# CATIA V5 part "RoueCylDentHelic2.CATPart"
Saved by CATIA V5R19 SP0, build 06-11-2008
Part number: Roue Cyl Denture Hélicoïdale2
Bounding box of the stored display mesh (mm): x -74.499 to 74.5, y -74.5 to 74.502, z -20.617 to 50
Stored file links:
  U:\Rendu_cfao_elguidj\RoueCylDentHelic2.CATPart
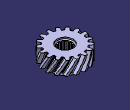
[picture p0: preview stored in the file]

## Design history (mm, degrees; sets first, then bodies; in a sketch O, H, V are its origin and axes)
External parameters (linked from other documents)
  External.Module = 7 mm
  External.Z = 17
  External.DiamPrimitif = 137.4094 mm {= External.ModuleApparent*External.Z}
  External.AnglePression = 20 deg
  External.x = 0
  External.DeportDenture = 0 mm {= External.x *External.ModuleApparent}
  External.DiamBase = 129.1226 mm {= External.DiamPrimitif *cos(External.AnglePression )}
  External.DiamPied = 119.9094 mm {= External.DiamPrimitif -2.5*External.Module +2*External.DeportDenture}
  External.DiamTete = 149 mm
  External.PhiPrimitif = 0.854 deg {= atan((sin(External.ThetaPrimitif*1rad)-External.ThetaPrimitif*cos(External.ThetaPrimitif*1rad))/(cos(External.ThetaPrimitif*1rad)+External.ThetaPrimitif*sin(External.ThetaPrimitif*1rad)))}
  External.PhiTete = 3.058 deg {= atan((sin(External.ThetaTete*1rad)-External.ThetaTete*cos(External.ThetaTete*1rad))/(cos(External.ThetaTete*1rad)+External.ThetaTete*sin(External.ThetaTete*1rad)))}
  External.PhiSymetrie = 5.2941 deg {= 180*1 deg/(2*External.Z )}
  External.CongePied = 2.66 mm {= 0.38*External.Module}
  External.AlphaCopie = 21.1765 deg {= 360*1 deg/External.Z}
  External.AlphaSymetrieCopie = 10.5882 deg {= External.AlphaCopie /2}
  External.LargeurDenture = 50 mm {= 50mm}
  External.ThetaPrimitif = 0.36397 {= sqrt(abs((External.DiamPrimitif*External.DiamPrimitif)/(External.DiamBase *External.DiamBase )-1))}
  External.ThetaTete = 0.575832 {= sqrt(abs((External.DiamTete*External.DiamTete)/(External.DiamBase *External.DiamBase )-1) )}
  External.Di = 133.266 mm {= (External.DiamBase +External.DiamPrimitif )/2}
  External.Thetai = 0.255358 {= sqrt(abs((External.Di*External.Di)/(External.DiamBase*External.DiamBase)-1))}
  External.Phii = 0.3061 deg {= atan((sin(External.Thetai*1rad)-External.Thetai*cos(External.Thetai*1rad))/(cos(External.Thetai*1rad)+External.Thetai*sin(External.Thetai*1rad)))}
  External.Dj = 143.2047 mm {= (External.DiamTete+External.DiamPrimitif)/2}
  External.Thetaj = 0.479598 {= sqrt(abs((External.Dj*External.Dj)/(External.DiamBase*External.DiamBase)-1))}
  External.Phij = 1.8567 deg {= atan((sin(External.Thetaj*1rad)-External.Thetaj*cos(External.Thetaj*1rad))/(cos(External.Thetaj*1rad)+External.Thetaj*sin(External.Thetaj*1rad)))}
  External.Dk = 131.1943 mm {= (External.Di+External.DiamBase)/2}
  External.Thetak = 0.179851 {= sqrt(abs((External.Dk*External.Dk)/(External.DiamBase*External.DiamBase)-1))}
  External.Phik = 0.109 deg {= atan((sin(External.Thetak*1rad)-External.Thetak*cos(External.Thetak*1rad))/(cos(External.Thetak*1rad)+External.Thetak*sin(External.Thetak*1rad)))}
  External.Dl = 135.3377 mm {= (External.DiamPrimitif+External.Di)/2}
  External.Thetal = 0.31398 {= sqrt(abs((External.Dl*External.Dl)/(External.DiamBase*External.DiamBase)-1))}
  External.Phil = 0.5585 deg {= atan((sin(External.Thetal*1rad)-External.Thetal*cos(External.Thetal*1rad))/(cos(External.Thetal*1rad)+External.Thetal*sin(External.Thetal*1rad)))}
  External.Dm = 140.307 mm {= (External.Dj+External.DiamPrimitif)/2}
  External.Thetam = 0.425136 {= sqrt(abs((External.Dm*External.Dm)/(External.DiamBase*External.DiamBase)-1))}
  External.Phim = 1.3264 deg {= atan((sin(External.Thetam*1rad)-External.Thetam*cos(External.Thetam*1rad))/(cos(External.Thetam*1rad)+External.Thetam*sin(External.Thetam*1rad)))}
  External.Dn = 146.1023 mm {= (External.DiamTete+External.Dj)/2}
  External.Thetan = 0.529429 {= sqrt(abs((External.Dn*External.Dn)/(External.DiamBase*External.DiamBase)-1))}
  External.Phin = 2.436 deg {= atan((sin(External.Thetan*1rad)-External.Thetan*cos(External.Thetan*1rad))/(cos(External.Thetan*1rad)+External.Thetan*sin(External.Thetan*1rad)))}
  External.AngleHelice = 30 deg
  External.ModuleApparent = 8.0829 mm {= External.Module /cos(External.AngleHelice )}
  External.SensDenture = 1
  External.LargeurDent = 45 mm {= round(PI*External.Module /sin(External.AngleHelice )/1mm)*1mm+1mm}
Body1 (main body)
  Sketch1 "EsquisseDent" on xy-plane, origin (0, 0, 0), H (1, 0, 0), V (0, 1, 0)
    construction circle A1 centre (0, 0) radius 68.7047
    construction circle A2 centre (0, 0) radius 64.5613
    construction circle A3 centre (0, 0) radius 59.9547
    construction circle A4 centre (0, 0) radius 74.5
    point P1 (64.5613, 0)
    construction line L1 (64.5613, 0) -> (0, 0)
    point P2 (68.6971, 1.024)
    construction line L2 (68.6971, 1.024) -> (0, 0)
    point P3 (74.3939, 3.9744)
    construction line L3 (74.3939, 3.9744) -> (0, 0)
    construction line L4 (64.5613, 0) -> (64.5613, 3.9367)
    point P4 (64.5613, 0)
    point P6 (60.4255, 1.024)
    construction line L5 (74.3939, 3.9744) -> (68.6971, 1.024)
    point P7 (71.5455, 2.4992)
    point P8 (57.5771, 2.4992)
    spline S1 through (57.5771, 2.4992) (60.4255, 1.024) (64.5613, 0) (65.597, 0.1248) (66.632, 0.356) (67.6656, 0.6596) (68.6971, 1.024) (70.1347, 1.6239) (71.5648, 2.3199) (72.9852, 3.1049) (74.3939, 3.9744)
    construction line L6 (0, 0) -> (5.2441, 0.5649)
    spline S2 through (56.7885, 9.82) (59.2574, 11.868) (63.0802, 13.7493) (64.1188, 13.8479) (65.1793, 13.8424) (66.2538, 13.7659) (67.3392, 13.6296) (68.8717, 13.3496) (70.4171, 12.9741) (71.9721, 12.5096) (73.5337, 11.9601)
    arc A5 centre (62.5641, -2.5174) radius 2.66 from (63.0483, 0.0982) to (59.9062, -2.4104) ccw
    point P11 (59.9062, -2.4104)
    arc A6 centre (0, 0) radius 74.5 from (74.3939, 3.9744) to (73.5337, 11.9601) ccw
    point P13 (73.5337, 11.9601)
    arc A7 centre (60.5927, 15.7836) radius 2.66 from (58.0186, 15.113) to (61.6229, 13.3311) ccw
    point P15 (58.0186, 15.113)
    construction line L7 (0, 0) -> (4.1018, 1.2334)
    construction line L8 (0, 0) -> (5.1105, -0.3968)
    point P19 (57.415, 17.265)
    arc A8 centre (0, 0) radius 59.9547 from (58.0186, 15.113) to (57.415, 17.265) ccw
    point P20 (59.7747, -4.6416)
    arc A9 centre (0, 0) radius 59.9547 from (59.7747, -4.6416) to (59.9062, -2.4104) ccw
    line L9 (57.415, 17.265) -> (0, 0)
    line L10 (59.7747, -4.6416) -> (0, 0)
    construction circle A10 centre (0, 0) radius 66.633
    construction line L11 (0, 0) -> (2.5698, 0.0137)
    point P22 (66.632, 0.356)
    construction circle A11 centre (0, 0) radius 71.6023
    construction line L12 (0, 0) -> (4.017, 0.1302)
    point P24 (71.5648, 2.3199)
    point P25 (71.5648, 2.3199)
    point P26 (70.4171, 12.9741)
    point P27 (65.1793, 13.8424)
    construction circle A12 centre (0, 0) radius 65.5971
    construction line L13 (0, 0) -> (48.2618, 0.0918)
    point P29 (64.1188, 13.8479)
    construction line L14 (0, 0) -> (63.6105, 6.852)
    point P31 (65.597, 0.1248)
    construction circle A13 centre (0, 0) radius 67.6688
    construction line L15 (0, 0) -> (57.3607, 0.5591)
    point P33 (67.6656, 0.6596)
    point P34 (66.2538, 13.7659)
    construction circle A14 centre (0, 0) radius 70.1535
    construction line L16 (0, 0) -> (65.6931, 1.5211)
    point P36 (70.1347, 1.6239)
    point P37 (68.8717, 13.3496)
    construction circle A15 centre (0, 0) radius 73.0512
    axis line L17 (0, 0) -> (59.2973, 2.5226)
    point P39 (71.9721, 12.5096)
    point P40 (72.9852, 3.1049)
    point P42 (57.5771, 2.4992)
    point P43 (60.4255, 1.024)
    point P44 (64.5613, 0)
    point P45 (68.6971, 1.024)
    point P46 (74.3939, 3.9744)
    point P47 (73.5337, 11.9601)
    point P48 (56.7885, 9.82)
    point P49 (67.3392, 13.6296)
    point P50 (63.0802, 13.7493)
    point P51 (59.2574, 11.868)
    point P52 (66.632, 0.356)
    point P53 (71.5648, 2.3199)
    point P54 (65.1793, 13.8424)
    point P55 (70.4171, 12.9741)
    point P56 (65.597, 0.1248)
    point P57 (64.1188, 13.8479)
    point P58 (67.6656, 0.6596)
    point P59 (66.2538, 13.7659)
    point P60 (70.1347, 1.6239)
    point P61 (68.8717, 13.3496)
    point P62 (72.9852, 3.1049)
    point P63 (71.9721, 12.5096)
    radius A1 = 68.7047 {= External.DiamPrimitif /2}
    radius A2 = 64.5613 {= External.DiamBase /2}
    radius A3 = 59.9547 {= External.DiamPied /2}
    radius A4 = 74.5 {= External.DiamTete /2}
    angle L2 L1 = 0.854 {= External.PhiPrimitif}
    angle L3 L1 = 3.058 {= External.PhiTete}
    angle L4 L1 = 90
    radius A5 = 2.66 {= External.CongePied}
    radius A7 = 2.66 {= External.CongePied}
    angle L7 L6 = 10.5882 {= External.AlphaSymetrieCopie}
    angle L2 L6 = 5.2941 {= External.PhiSymetrie}
    radius A10 = 66.633 {= External.Di /2}
    angle L11 L1 = 0.3061 {= External.Phii}
    radius A11 = 71.6023 {= External.Dj /2}
    angle L12 L1 = 1.8567 {= External.Phij}
    radius A12 = 65.5971 {= External.Dk/2}
    angle L13 L1 = 0.109 {= External.Phik}
    angle L14 L2 = 5.2941 {= External.PhiSymetrie}
    radius A13 = 67.6688 {= External.Dl /2}
    angle L15 L1 = 0.5585 {= External.Phil}
    radius A14 = 70.1535 {= External.Dm /2}
    angle L16 L1 = 1.3264 {= External.Phim}
    radius A15 = 73.0512 {= External.Dn/2}
    angle L17 L1 = 2.436 {= External.Phin}
    coincidence: P1 A2, P1 H, P2 A1, P3 A4, P4 A2, P7 L5, P42 P8, P43 P6, P44 P1, P45 L5, P45 L2, P46 L5, P46 L3, P11 A3, P47 P13, P15 A3, P19 L7, P19 A3, P20 L8, P20 A3, P3 P46, P22 L11, P22 A10, P52 P22, P24 L12, P24 A11, P53 P24, P25 P53, P54 P27, P55 P26, P31 L13, P31 A12, P56 P31, P57 P29, P33 L15, P33 A13, P58 P33, P59 P34, P36 L16, P36 A14, P60 P36, P61 P37, P40 L17, P40 A15, P62 P40, P63 P39, O L9, O L10
    horizontal: L1 H
    tangency: L4 A2, A5 A3, A5 S1, A7 A3, A7 S2, A8 A5, A9 A5
    symmetry: P6 P2 L4, P8 P7 L4, P46 P47 L6, P42 P48 L6, P45 P49 L6, P44 P50 L6, P43 P51 L6, L8 L7 L6, P26 P25 L6, P27 P22 L6, P29 P31 L14, P34 P33 L14, P37 P36 L14, P39 P40 L14
    midpoint: P7 L5
    parallelism: L9 L7, L10 L8
    concentricity: A10 A2, A11 A1
  Translate1: ToTransfor Sketch1, Direction (0, 0, 1), Length 50 {= External.LargeurDenture}
  Rotate1: ToTransfor Translate1, Axis Z axis, Angle 22.7906 {= External.SensDenture *atan(2*External.LargeurDenture/External.DiamPrimitif*tan(External.AngleHelice))}
  Translate2: ToTransfor Sketch1, Direction (0, 0, 1), Length 25 {= External.LargeurDenture/2}
  Rotate2: ToTransfor Translate2, Axis Z axis, Angle 11.8644 {= External.SensDenture *atan(External.LargeurDenture/(External.DiamPrimitif)*tan(External.AngleHelice))}
  Translate3: ToTransfor Sketch1, Direction (0, 0, 1), Length 37.5 {= 3/4*External.LargeurDenture}
  Rotate3: ToTransfor Translate3, Axis Z axis, Angle 17.491 {= External.SensDenture*atan(3*External.LargeurDenture/(2*External.DiamPrimitif)*tan(External.AngleHelice))}
  Translate4: ToTransfor Sketch1, Direction (0, 0, 1), Length 12.5 {= External.LargeurDenture/4}
  Rotate4: ToTransfor Translate4, Axis Z axis, Angle 5.9965 {= External.SensDenture*atan(External.LargeurDenture/(2*External.DiamPrimitif)*tan(External.AngleHelice))}
  Loft1: solid, Sections (Sketch1; Rotate4; Rotate2; Rotate3; Rotate1)
  CircPattern1: of the body so far, instances 17 {= External.Z}, angular step 21.1765 {= External.AlphaCopie}, axis from Z axis
  Plane1: type Offset, RefPlane xy-plane, Offset 50 {= External.LargeurDenture}, reversed
  Sketch2 on Plane1, origin (0, 0, -50), H (1, 0, 0), V (0, 1, 0)
    circle A1 centre (0, 0) radius 29
    radius A1 = 29 {= int(External.DiamPied/(4mm))*1mm}
  Pocket1: profile Sketch2, direction (0, 0, 1), length 150 {= 3*External.LargeurDenture}
  DatumCurve1 to DatumCurve3
  Sketch3 on yz-plane, origin (0, 0, 0), H (0, 1, 0), V (0, 0, 1)
    point P1 (42.5, 0)
    line L1 (42.5, 0) -> (42.5, -20.617)
    line L2 (42.5, -20.617) -> (29, -20.617)
    point P3 (29, -20.617)
    line L3 (29, -20.617) -> (25, -13.6888)
    line L4 (25, -13.6888) -> (25, 42.6906)
    line L5 (25, 42.6906) -> (29, 45)
    point P6 (29, 45)
    line L6 (42.5, 0) -> (29, 0)
    point P7 (29, 0)
    line L7 (29, 0) -> (29, 45)
    reference projected line E1 (0, -270.203) -> (0, 469.4047) from edge of DatumCurve1
    reference projected line E2 (0, -270.203) -> (0, 469.4047) from edge of DatumCurve2
    point P8 (29, 0)
    reference intersected line E3 (-59.9784, 50) -> (74.5, 50) from face of CircPattern1
    distance L1 E1 = 42.5
    angle L4 L5 = 60
    angle L3 L4 = 30
    length L1 = 20.617
    distance L4 E2 = 25
    distance P6 E3 = 5
    coincidence: P1 H, P7 P8, P3 L7
    vertical: L1 V, L4 V, L7 V
    horizontal: L2 H, L6 H
    fix: P8
  Shaft1: profile Sketch3, axis edge of DatumCurve3, angle 360
  Plane2: stored without definition
  Sketch4 on xy-plane, origin (0, 0, 0), H (1, 0, 0), V (0, 1, 0)
    arc A1 centre (0, 0) radius 20.1556 from (-2.5, 20) to (-5.2167, 19.4689) ccw
    construction line L1 (0, 0) -> (0, 22.1914)
    point P2 (2.5, 24)
    line L2 (2.5, 24) -> (-2.5, 24)
    line L3 (-2.5, 24) -> (-2.5, 20)
    line L4 (2.5, 20) -> (2.5, 24)
    point P3 (-2.5, 24)
    point P4 (2.5, 20)
    point P5 (-2.5, 20)
    construction line L5 (4.2245, -15.766) -> (-5.8305, 21.7596)
    construction line L6 (-5.8201, -21.7207) -> (5.9156, 22.0773)
    construction line L7 (17.7406, -17.7406) -> (-11.7329, 11.7329)
    construction line L8 (16.2956, -4.3664) -> (-15.3401, 4.1104)
    point P14 (-5.2167, 19.4689)
    arc A2 centre (0, 0) radius 20.1556 from (5.2167, 19.4689) to (2.5, 20) ccw
    point P15 (5.2167, 19.4689)
    point P16 (-5.2167, 19.4689)
    point P17 (-7.8349, 18.5705)
    arc A3 centre (0, 0) radius 20.1556 from (-7.8349, 18.5705) to (-5.2167, 19.4689) cw
    point P19 (-9.8349, 22.0346)
    line L9 (-9.8349, 22.0346) -> (-7.8349, 18.5705)
    point P20 (-14.1651, 19.5346)
    line L10 (-14.1651, 19.5346) -> (-9.8349, 22.0346)
    point P21 (-12.1651, 16.0705)
    line L11 (-12.1651, 16.0705) -> (-14.1651, 19.5346)
    point P22 (-14.2522, 14.2522)
    arc A4 centre (0, 0) radius 20.1556 from (-14.2522, 14.2522) to (-12.1651, 16.0705) cw
    point P23 (-20, -2.5)
    point P24 (-19.4689, -5.2167)
    arc A5 centre (0, 0) radius 20.1556 from (-19.4689, -5.2167) to (-20, -2.5) cw
    point P26 (-24, -2.5)
    line L12 (-20, -2.5) -> (-24, -2.5)
    point P27 (-24, 2.5)
    line L13 (-24, -2.5) -> (-24, 2.5)
    point P28 (-20, 2.5)
    line L14 (-24, 2.5) -> (-20, 2.5)
    point P29 (-19.4689, 5.2167)
    arc A6 centre (0, 0) radius 20.1556 from (-20, 2.5) to (-19.4689, 5.2167) cw
    point P30 (-19.4689, 5.2167)
    point P31 (-18.5705, 7.8349)
    arc A7 centre (0, 0) radius 20.1556 from (-18.5705, 7.8349) to (-19.4689, 5.2167) ccw
    point P33 (-22.0346, 9.8349)
    line L15 (-22.0346, 9.8349) -> (-18.5705, 7.8349)
    point P34 (-19.5346, 14.1651)
    line L16 (-19.5346, 14.1651) -> (-22.0346, 9.8349)
    point P35 (-16.0705, 12.1651)
    line L17 (-16.0705, 12.1651) -> (-19.5346, 14.1651)
    point P36 (-14.2522, 14.2522)
    arc A8 centre (0, 0) radius 20.1556 from (-14.2522, 14.2522) to (-16.0705, 12.1651) ccw
    axis line L18 (-19.4689, -5.2167) -> (23.4606, 6.2862)
    point P38 (-7.8349, -18.5705)
    point P39 (-5.2167, -19.4689)
    arc A9 centre (0, 0) radius 20.1556 from (-5.2167, -19.4689) to (-7.8349, -18.5705) cw
    point P41 (-9.8349, -22.0346)
    line L19 (-7.8349, -18.5705) -> (-9.8349, -22.0346)
    point P42 (-14.1651, -19.5346)
    line L20 (-9.8349, -22.0346) -> (-14.1651, -19.5346)
    point P43 (-12.1651, -16.0705)
    line L21 (-14.1651, -19.5346) -> (-12.1651, -16.0705)
    point P44 (-14.2522, -14.2522)
    arc A10 centre (0, 0) radius 20.1556 from (-12.1651, -16.0705) to (-14.2522, -14.2522) cw
    point P45 (-14.2522, -14.2522)
    point P46 (-16.0705, -12.1651)
    arc A11 centre (0, 0) radius 20.1556 from (-16.0705, -12.1651) to (-14.2522, -14.2522) ccw
    point P48 (-19.5346, -14.1651)
    line L22 (-19.5346, -14.1651) -> (-16.0705, -12.1651)
    point P49 (-22.0346, -9.8349)
    line L23 (-22.0346, -9.8349) -> (-19.5346, -14.1651)
    point P50 (-18.5705, -7.8349)
    line L24 (-18.5705, -7.8349) -> (-22.0346, -9.8349)
    point P51 (-19.4689, -5.2167)
    arc A12 centre (0, 0) radius 20.1556 from (-19.4689, -5.2167) to (-18.5705, -7.8349) ccw
    point P52 (7.8349, 18.5705)
    point P53 (5.2167, 19.4689)
    arc A13 centre (0, 0) radius 20.1556 from (5.2167, 19.4689) to (7.8349, 18.5705) cw
    point P55 (9.8349, 22.0346)
    line L25 (7.8349, 18.5705) -> (9.8349, 22.0346)
    point P56 (14.1651, 19.5346)
    line L26 (9.8349, 22.0346) -> (14.1651, 19.5346)
    point P57 (12.1651, 16.0705)
    line L27 (14.1651, 19.5346) -> (12.1651, 16.0705)
    point P58 (14.2522, 14.2522)
    arc A14 centre (0, 0) radius 20.1556 from (12.1651, 16.0705) to (14.2522, 14.2522) cw
    point P59 (14.2522, 14.2522)
    point P60 (16.0705, 12.1651)
    arc A15 centre (0, 0) radius 20.1556 from (16.0705, 12.1651) to (14.2522, 14.2522) ccw
    point P62 (19.5346, 14.1651)
    line L28 (19.5346, 14.1651) -> (16.0705, 12.1651)
    point P63 (22.0346, 9.8349)
    line L29 (22.0346, 9.8349) -> (19.5346, 14.1651)
    point P64 (18.5705, 7.8349)
    line L30 (18.5705, 7.8349) -> (22.0346, 9.8349)
    point P65 (19.4689, 5.2167)
    arc A16 centre (0, 0) radius 20.1556 from (19.4689, 5.2167) to (18.5705, 7.8349) ccw
    point P66 (20, 2.5)
    point P67 (19.4689, 5.2167)
    arc A17 centre (0, 0) radius 20.1556 from (19.4689, 5.2167) to (20, 2.5) cw
    point P69 (24, 2.5)
    line L31 (20, 2.5) -> (24, 2.5)
    point P70 (24, -2.5)
    line L32 (24, 2.5) -> (24, -2.5)
    point P71 (20, -2.5)
    line L33 (24, -2.5) -> (20, -2.5)
    point P72 (19.4689, -5.2167)
    arc A18 centre (0, 0) radius 20.1556 from (20, -2.5) to (19.4689, -5.2167) cw
    point P73 (19.4689, -5.2167)
    point P74 (18.5705, -7.8349)
    arc A19 centre (0, 0) radius 20.1556 from (18.5705, -7.8349) to (19.4689, -5.2167) ccw
    point P76 (22.0346, -9.8349)
    line L34 (22.0346, -9.8349) -> (18.5705, -7.8349)
    point P77 (19.5346, -14.1651)
    line L35 (19.5346, -14.1651) -> (22.0346, -9.8349)
    point P78 (16.0705, -12.1651)
    line L36 (16.0705, -12.1651) -> (19.5346, -14.1651)
    point P79 (14.2522, -14.2522)
    arc A20 centre (0, 0) radius 20.1556 from (14.2522, -14.2522) to (16.0705, -12.1651) ccw
    point P80 (12.1651, -16.0705)
    point P81 (14.2522, -14.2522)
    arc A21 centre (0, 0) radius 20.1556 from (14.2522, -14.2522) to (12.1651, -16.0705) cw
    point P83 (14.1651, -19.5346)
    line L37 (12.1651, -16.0705) -> (14.1651, -19.5346)
    point P84 (7.8349, -18.5705)
    point P85 (9.8349, -22.0346)
    line L38 (9.8349, -22.0346) -> (7.8349, -18.5705)
    point P86 (5.2167, -19.4689)
    arc A22 centre (0, 0) radius 20.1556 from (7.8349, -18.5705) to (5.2167, -19.4689) cw
    point P87 (5.2167, -19.4689)
    point P88 (2.5, -20)
    arc A23 centre (0, 0) radius 20.1556 from (2.5, -20) to (5.2167, -19.4689) ccw
    point P90 (2.5, -24)
    line L39 (2.5, -24) -> (2.5, -20)
    point P91 (-2.5, -24)
    line L40 (-2.5, -24) -> (2.5, -24)
    point P92 (-2.5, -20)
    line L41 (-2.5, -20) -> (-2.5, -24)
    point P93 (-5.2167, -19.4689)
    arc A24 centre (0, 0) radius 20.1556 from (-5.2167, -19.4689) to (-2.5, -20) ccw
    line L42 (14.1651, -19.5346) -> (9.8349, -22.0346)
    circle A25 centre (0, 0) radius 25
    length L3 = 4
    length L4 = 4
    distance L4 L1 = 2.5
    distance H L2 = 24
    angle L8 L7 = 30
    radius A25 = 25
    vertical: L1 V, L3 V, L4 V
    horizontal: L2 H
    coincidence: L5 O, L6 O, L7 O, L8 O, L5 P14, L6 P15, A1 A2, L18 O, P14 P16, P15 P53, P22 P36, P24 P51, P29 P30, P39 P93, P44 P45, P58 P59, P65 P67, P72 P73, P79 P81, P86 P87
    symmetry: P14 P16 L5, P5 P17 L5, A1 A3 L5, P3 P19 L5, L3 L9 L5, P2 P20 L5, L2 L10 L5, P4 P21 L5, L4 L11 L5, P15 P22 L5, A2 A4 L5, P4 P23 L7, P15 P24 L7, A2 A5 L7, P2 P26 L7, L4 L12 L7, P3 P27 L7, L2 L13 L7, P5 P28 L7, L3 L14 L7, P14 P29 L7, A1 A6 L7, P16 P30 L7, P17 P31 L7, A3 A7 L7, P19 P33 L7, L9 L15 L7, P20 P34 L7, L10 L16 L7, P21 P35 L7, L11 L17 L7, P22 P36 L7, A4 A8 L7, P35 P38 L18, P36 P39 L18, A8 A9 L18, P34 P41 L18, L17 L19 L18, P33 P42 L18, L16 L20 L18, P31 P43 L18, L15 L21 L18, P30 P44 L18, A7 A10 L18, P29 P45 L18, P28 P46 L18, A6 A11 L18, P27 P48 L18, L14 L22 L18, P26 P49 L18, L13 L23 L18, P23 P50 L18, L12 L24 L18, P24 P51 L18, A5 A12 L18, P4 P52 L6, P15 P53 L6, A2 A13 L6, P2 P55 L6, L4 L25 L6, P3 P56 L6, L2 L26 L6, P5 P57 L6, L3 L27 L6, P14 P58 L6, A1 A14 L6, P16 P59 L6, P17 P60 L6, A3 A15 L6, P19 P62 L6, L9 L28 L6, P20 P63 L6, L10 L29 L6, P21 P64 L6, L11 L30 L6, P22 P65 L6, A4 A16 L6, P35 P66 L6, P36 P67 L6, A8 A17 L6, P34 P69 L6, L17 L31 L6, P33 P70 L6, L16 L32 L6, P31 P71 L6, L15 L33 L6, P30 P72 L6, A7 A18 L6, P29 P73 L6, P28 P74 L6, A6 A19 L6, P27 P76 L6, L14 L34 L6, P26 P77 L6, L13 L35 L6, P23 P78 L6, L12 L36 L6, P24 P79 L6, A5 A20 L6, P50 P80 L6, P51 P81 L6, A12 A21 L6, P49 P83 L6, L24 L37 L6, P46 P84 L6, P48 P85 L6, L22 L38 L6, P45 P86 L6, A11 A22 L6, P44 P87 L6, P43 P88 L6, A10 A23 L6, P42 P90 L6, L21 L39 L6, P41 P91 L6, L20 L40 L6, P38 P92 L6, L19 L41 L6, P39 P93 L6, A9 A24 L6, L23 L42 L6
  Pad1: profile Sketch4, direction (0, 0, -1), length 13.689, opposite side length 42.691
